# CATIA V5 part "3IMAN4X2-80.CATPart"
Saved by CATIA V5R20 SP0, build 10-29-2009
Part number: 3IMAN4X2-80
Revision: ANY
Definition: UNKNOWN
Nomenclature: 3IMAN4X2-80
Source: Unknown
Bounding box of the stored display mesh (mm): x -2 to 2, y -2 to 2, z 0 to 2
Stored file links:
  C:\Users\Utente\Desktop\IO LAVORO\3D X SITO CF\CUMSA\3D files PR.233230\PR 263230\3IMAN4X2-80.CATPart
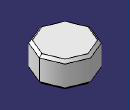
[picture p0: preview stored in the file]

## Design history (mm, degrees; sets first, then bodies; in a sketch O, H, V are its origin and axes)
Body1 "Chaflán1" (main body)
  Solid1: solid without history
